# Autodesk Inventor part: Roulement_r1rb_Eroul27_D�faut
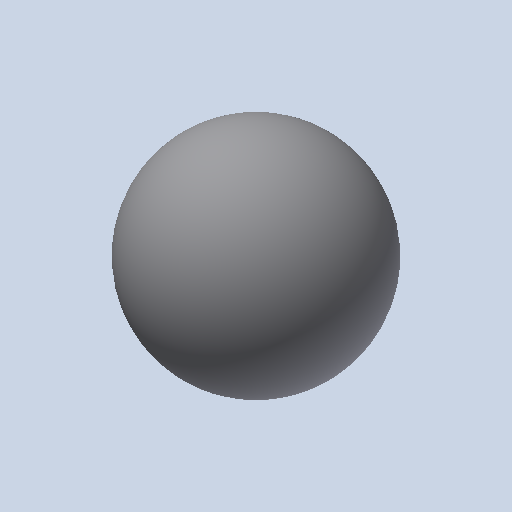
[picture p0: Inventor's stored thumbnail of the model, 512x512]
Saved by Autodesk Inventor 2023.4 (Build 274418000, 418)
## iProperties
Created: 2011-01
Part Number: Roulement_r1rb_Eroul27_D�faut
Document SubType Name: Modeling
Designer: eric
Density: 1 g/cm^3
Mass: 0.0579058 g
Surface Area: 0.723823 cm^2
Volume: 0.0579058 cm^3
Material: Générique
Appearance: Par défaut
Author: eric
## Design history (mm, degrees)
feature "Base1"
node "Corps solides"
node "Corps surfaciques"
node "Solide1"
